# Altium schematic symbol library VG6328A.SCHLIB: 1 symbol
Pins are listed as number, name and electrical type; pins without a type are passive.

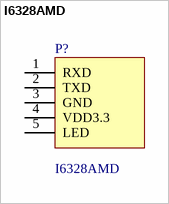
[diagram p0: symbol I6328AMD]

## I6328AMD
designator P?
pins: 1 RXD, 2 TXD, 3 GND, 4 VDD3.3, 5 LED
